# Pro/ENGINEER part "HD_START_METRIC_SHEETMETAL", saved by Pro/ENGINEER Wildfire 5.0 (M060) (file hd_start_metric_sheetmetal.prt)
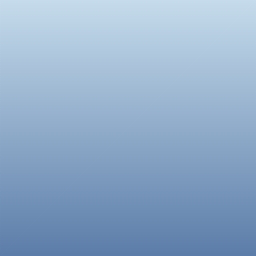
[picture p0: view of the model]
Units: hd_metric; MM, KILOGRAM, SECS
Materials in the file: DEFAULT

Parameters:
  DRW_UNITS = "METRIC"
  TOL_NAME = "MILLIMETERS"
  SUR = "6.3"
  LINEAR_TOL_0 = "1.0"
  PTC_MATERIAL_NAME = "DEFAULT"

Other parameters: SMT_THICKNESS

Other named items: CS_DEF, PT_ORIG, SIDE, TOP, FRONT

Layers: ANNOT, AXES, COSMETIC, CS, CURVES, DATUMS, DEF_CS, DEF_DATUMS, GEOM_CRVS, GEOM_DATUMS, GEOM_PNTS, PTS, SURFS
